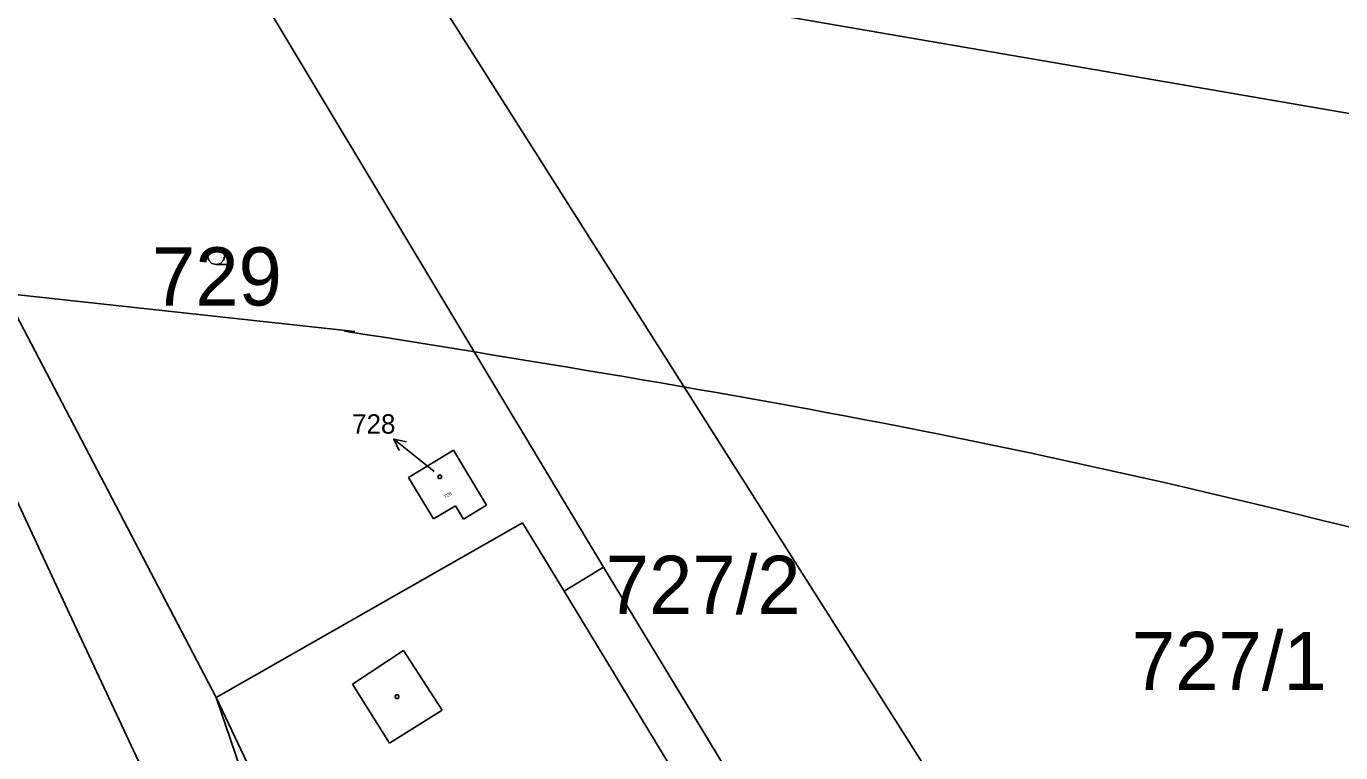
# Model space of a CAD drawing. Extents: x -510185 to -506993, y -1126306 to -1123642.
# Drawn here: x -508329.2 to -508214.1, y -1126219.2 to -1126155.6 of the extents above; entities that cross this region are included whole.
import ezdxf

# ---------------------------------------------------------------- set-up
doc = ezdxf.new("R2010")
doc.units = 0
for name, color, linetype in [('ochranná pásma', 7, 'Continuous'), ('parcelni hranice', 7, 'Continuous'), ('u_dráha', 7, 'Continuous'), ('ˇ2', 7, 'Continuous'), ('ˇ3', 7, 'Continuous'), ('ˇ4', 7, 'Continuous'), ('ˇ5', 7, 'Continuous'), ('ˇ7', 7, 'Continuous')]:
    doc.layers.add(name, color=color, linetype=linetype)

msp = doc.modelspace()

# ---------------------------------------------------------------- linework, layer by layer
at = {"layer": 'ochranná pásma'}
msp.add_line((-508356.03, -1126176.27), (-508300.45, -1126182.28), dxfattribs=at)
msp.add_spline([(-508301.36, -1126182.25), (-508249.27, -1126191.29), (-508186.12, -1126206.67), (-508130.63, -1126224.11), (-508076.15, -1126245.19)], degree=3, dxfattribs=at)
at = {"layer": 'parcelni hranice'}
for p, q in [((-508312.53, -1126146.5), (-508278.67, -1126202.95)), ((-508224.13, -1126262.08), (-508295.78, -1126148.98)), ((-508295.78, -1126148.98), (-508235.55, -1126159.37)), ((-508235.55, -1126159.37), (-508200.75, -1126165.39)), ((-508312.6, -1126214.35), (-508334.51, -1126172.44)), ((-508339.6, -1126176.65), (-508325.22, -1126207.46)), ((-508295.74, -1126195.07), (-508291.81, -1126192.7)), ((-508291.81, -1126192.7), (-508288.9, -1126197.52)), ((-508293.54, -1126198.71), (-508295.74, -1126195.07)), ((-508291.63, -1126197.56), (-508293.54, -1126198.71)), ((-508290.91, -1126198.73), (-508291.63, -1126197.56)), ((-508288.9, -1126197.52), (-508290.91, -1126198.73)), ((-508285.75, -1126199.06), (-508312.6, -1126214.35)), ((-508282.12, -1126205.04), (-508285.75, -1126199.06)), ((-508278.67, -1126202.95), (-508282.12, -1126205.04)), ((-508278.67, -1126202.95), (-508246.09, -1126256.56)), ((-508251.41, -1126255.58), (-508282.12, -1126205.04)), ((-508325.22, -1126207.46), (-508315.09, -1126229.11)), ((-508306.5, -1126227.09), (-508312.6, -1126214.35))]:
    msp.add_line(p, q, dxfattribs=at)
at = {"layer": 'u_dráha'}
for points in [[(-508293.25, -1126118.3), (-508236.19, -1126128.22), (-508168.72, -1126144.46), (-508109.1, -1126162.38), (-508050.52, -1126184.09)], [(-508294, -1126122.63), (-508237.03, -1126132.52), (-508170.01, -1126148.84), (-508110.79, -1126167.45), (-508052.7, -1126189.93)]]:
    msp.add_spline(points, degree=3, dxfattribs=at)
at = {"layer": 'ˇ3'}
msp.add_lwpolyline([(-508312.59, -1126176.43), (-508312.97, -1126176.33), (-508313.24, -1126176.05), (-508313.34, -1126175.68), (-508313.24, -1126175.3), (-508312.97, -1126175.03), (-508312.59, -1126174.93), (-508312.22, -1126175.03), (-508311.94, -1126175.3), (-508311.84, -1126175.68), (-508311.94, -1126176.05), (-508312.22, -1126176.33), (-508312.59, -1126176.43), (-508311.59, -1126176.43)], dxfattribs=at)
at = {"layer": 'ˇ4'}
for p, q in [((-508300.66, -1126213.19), (-508296.17, -1126210.25)), ((-508296.17, -1126210.25), (-508292.8, -1126215.45)), ((-508297.41, -1126218.35), (-508300.66, -1126213.19)), ((-508312.6, -1126214.35), (-508308.02, -1126227.76)), ((-508292.8, -1126215.45), (-508297.41, -1126218.35))]:
    msp.add_line(p, q, dxfattribs=at)
at = {"layer": 'ˇ5'}
for points in [[(-508292.91, -1126194.88), (-508292.83, -1126195.03), (-508292.91, -1126195.18), (-508293.09, -1126195.18), (-508293.17, -1126195.03), (-508293.09, -1126194.88)], [(-508296.66, -1126214.13), (-508296.58, -1126214.28), (-508296.66, -1126214.43), (-508296.84, -1126214.43), (-508296.92, -1126214.28), (-508296.84, -1126214.13)]]:
    msp.add_lwpolyline(points, close=True, dxfattribs=at)
at = {"layer": 'ˇ7'}
msp.add_line((-508293.5, -1126194.56), (-508294.69, -1126193.59), dxfattribs=at)
for points in [[(-508297.03, -1126191.71), (-508294.69, -1126193.59)], [(-508296.56, -1126192.72), (-508297.03, -1126191.71), (-508295.93, -1126191.95)]]:
    msp.add_lwpolyline(points, dxfattribs=at)

# ---------------------------------------------------------------- texts
at = {"layer": 'ˇ2'}
for s, p in [('729', (-508318.21, -1126180.02)), ('727/2', (-508278.47, -1126207.04)), ('727/1', (-508232.39, -1126213.71))]:
    msp.add_text(s, height=5.1, dxfattribs=at).set_placement(p)
msp.add_text('728', height=0.3, rotation=30.5959, dxfattribs=at).set_placement((-508292.52, -1126196.93))
at = {"layer": 'ˇ7'}
msp.add_text('728', height=1.7, dxfattribs=at).set_placement((-508300.68, -1126191.24))

doc.saveas('drawing.dxf')
